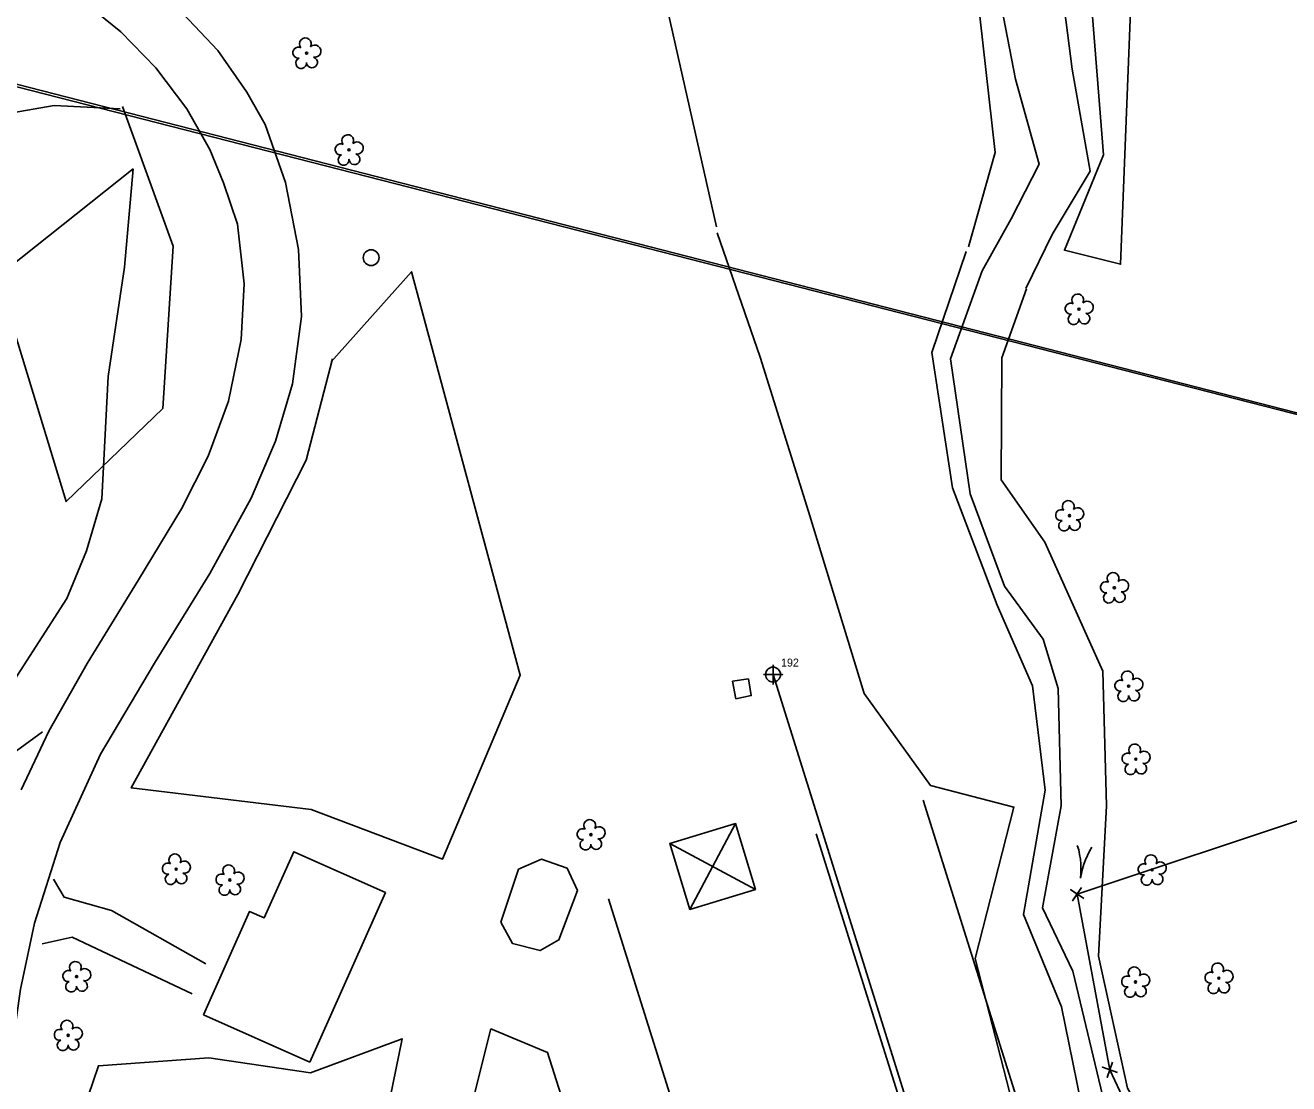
# Model space of a CAD drawing. Extents: x 1380524 to 1382335, y 594765 to 596944.
# Drawn here: x 1381171.1 to 1381565.9, y 595887.1 to 596218 of the extents above; entities that cross this region are included whole.
import ezdxf

# ---------------------------------------------------------------- set-up
doc = ezdxf.new("R2010")
doc.units = 0
for name, color, linetype in [('DTM Contours Major', 7, 'Continuous'), ('DTM Contours Major Text', 7, 'Continuous'), ('DTM Contours Minor Text', 7, 'Continuous'), ('Exist Hydro Jurisdictional Stream or Body of Water', 7, 'Continuous'), ('Exist Roads EOP', 7, 'Continuous'), ('Exist Structure Major Bridge WW', 7, 'Continuous'), ('Exist Utilities Gas UG Line', 7, 'Continuous'), ('Exist Utilities Gas UG Line Cogo Number', 7, 'Continuous'), ('Exist Utilities Gas UG Line Cogo Point CELL', 7, 'Continuous'), ('Exist Utilities Power Tower Text', 7, 'Continuous'), ('Prop Drainage Ditch Base Lines', 7, 'Continuous'), ('Prop Drainage Structure Box Number Symbol CELL', 7, 'Continuous'), ('Prop Drainage Structure Pipe Elbow CELL', 7, 'Continuous'), ('Prop Drainage Structure Plot Symbol 20 Scale CELL', 7, 'Continuous'), ('Prop Earthen Structure Cut Ditch Special Detail Label', 7, 'Continuous'), ('Prop Earthen Structure Ditch Flow Line', 7, 'Continuous'), ('Prop Earthen Structure V Ditch Lateral Detail Label', 7, 'Continuous'), ('Prop Erosion Rip Rap At Embankment Detail CELL', 7, 'Continuous'), ('Prop Plan Preparation Design Box Number Symbol CELL', 7, 'Continuous')]:
    doc.layers.add(name, color=color, linetype=linetype)

# ---------------------------------------------------------------- blocks, each defined once
blk = doc.blocks.new('EXIST VEGETATION TREE')
at = {"layer": 'Prop Erosion Rip Rap At Embankment Detail CELL'}
blk.add_line((0, 0), (0, 0), dxfattribs=at)
blk.add_circle((0, 0), 0.00652, dxfattribs=at)
for centre, radius, start, end in [((-0.0077, 0.0575), 0.0371, 330.16508, 219.71335), ((-0.0521, 0.0031), 0.0345, 62.66361, 279.3457), ((0.051, 0.0118), 0.038, 257.1011, 134.19993), ((-0.0341, -0.0624), 0.0338, 111.56708, 6.23104), ((0.0335, -0.058), 0.034, 181.28216, 74.55999)]:
    blk.add_arc(centre, radius, start, end, dxfattribs=at)
blk = doc.blocks.new('EXIST UTILITIES OTHER POLE')
at = {"layer": 'DTM Contours Major Text'}
blk.add_circle((0, 0), 0.0493, dxfattribs=at)
blk = doc.blocks.new('EXIST HYDRO STREAM FLOW ARROW')
at = {"layer": 'DTM Contours Minor Text'}
blk.add_line((0, 0), (0, 0), dxfattribs=at)
for points in [[(-0.1, 0.04575), (-0.07325, 0.03375), (-0.04475, 0.0245), (-0.0165, 0.01575), (0.01175, 0.0095), (0.041, 0.00475), (0.07075, 0.0015), (0.1, 0)], [(-0.1, -0.04575), (-0.07325, -0.03375), (-0.04475, -0.0245), (-0.0165, -0.01575), (0.01175, -0.0095), (0.041, -0.00475), (0.07075, -0.0015), (0.1, 0)]]:
    blk.add_lwpolyline(points, dxfattribs=at)

msp = doc.modelspace()

# ---------------------------------------------------------------- linework, layer by layer
at = {"layer": 'DTM Contours Major'}
msp.add_lwpolyline([(1381372.49, 595962.18), (1381378.72, 595941.62), (1381399.28, 595947.85), (1381393.05, 595968.41), (1381372.49, 595962.18), (1381399.28, 595947.85), (1381393.05, 595968.41), (1381378.72, 595941.62)], dxfattribs=at)
at = {"layer": 'Exist Hydro Jurisdictional Stream or Body of Water'}
for points in [[(1381483.77, 596135.72), (1381491.96, 596152.52), (1381503.81, 596172.33), (1381498.26, 596204.27), (1381493.33, 596242.46), (1381489.5, 596270.15), (1381491.18, 596292.87), (1381479.48, 596322.14), (1381454.47, 596352.84), (1381438.58, 596366.23), (1381425.98, 596394.97), (1381414.1, 596436.71), (1381399.5, 596471.74), (1381382.49, 596504.52), (1381368.62, 596529.32), (1381356.86, 596549.69), (1381340.72, 596592.72), (1381332.5, 596625.31), (1381329.08, 596649.3), (1381323.28, 596668.67)], [(1381470.05, 596141.17), (1381479.15, 596157.42), (1381487.89, 596174.59), (1381480.55, 596201.17), (1381473.06, 596240.03), (1381476.26, 596270.23), (1381479.45, 596291.3), (1381466.84, 596309.68), (1381447.4, 596346.85), (1381431.33, 596360.89), (1381418.79, 596391.67), (1381403.92, 596432.5), (1381387.45, 596465.68), (1381371.16, 596500.46), (1381359.03, 596523.24), (1381345.11, 596544.14), (1381332.16, 596589.54), (1381322.88, 596621.8), (1381316.31, 596646.98), (1381314.3, 596666.4)], [(1381577.96, 595605.83), (1381583.71, 595643.65), (1381597.79, 595698.93), (1381598.19, 595737), (1381590.93, 595758.1), (1381566.71, 595783.08), (1381549.63, 595827.2), (1381521.68, 595855.93), (1381508.31, 595880.93), (1381498.43, 595922.32), (1381488.98, 595942.12), (1381494.82, 595973.98), (1381493.85, 596010.61), (1381489.16, 596026.09), (1381477.05, 596042.66), (1381466.32, 596071.54), (1381460.24, 596113.74), (1381470.05, 596141.17)], [(1381591.28, 595608.86), (1381593.5, 595640.64), (1381608.3, 595697.05), (1381607.14, 595736.14), (1381600.89, 595770.21), (1381575.06, 595793.44), (1381555.94, 595831.43), (1381528.67, 595862.58), (1381515.5, 595885.72), (1381506.46, 595926.94), (1381508.98, 595973.98), (1381507.81, 596016.05), (1381489.64, 596056.36), (1381476.02, 596075.92), (1381476.25, 596113.98), (1381483.98, 596135.61)]]:
    msp.add_lwpolyline(points, dxfattribs=at)
at = {"layer": 'Exist Roads EOP'}
for points in [[(1381638.84, 595379.18), (1381451.62, 595975.74)], [(1381605.45, 595368.7), (1381418.22, 595965.25)], [(1381540.57, 595348.34), (1381353.34, 595944.89)]]:
    msp.add_lwpolyline(points, dxfattribs=at)
at = {"layer": 'Exist Structure Major Bridge WW'}
for p, q in [((1381499.76, 595946.4), (1381499.76, 595946.4)), ((1381510.01, 595891.46), (1381510.01, 595891.46))]:
    msp.add_line(p, q, dxfattribs=at)
for points in [[(1381501.82, 595944.98), (1381497.7, 595947.81), (1381499.76, 595946.4), (1381498.35, 595944.33), (1381501.17, 595948.46)], [(1381512.36, 595890.61), (1381507.66, 595892.3), (1381510.01, 595891.46), (1381509.16, 595889.11), (1381510.86, 595893.81)]]:
    msp.add_lwpolyline(points, dxfattribs=at)
at = {"layer": 'Exist Utilities Gas UG Line'}
msp.add_lwpolyline([(1381540.8, 595580.17), (1381404.76, 596015.01)], dxfattribs=at)
at = {"layer": 'Exist Utilities Gas UG Line Cogo Point CELL'}
msp.add_lwpolyline([(1381404.76, 596018.01), (1381404.76, 596012.01), (1381404.76, 596015.01), (1381407.76, 596015.01), (1381401.76, 596015.01)], dxfattribs=at)
msp.add_circle((1381404.76, 596015.01), 2.34, dxfattribs=at)
at = {"layer": 'Exist Utilities Power Tower Text'}
for p, q in [((1381499.76, 595946.4), (1381765.24, 596034.56)), ((1381510.01, 595891.46), (1381499.76, 595946.4)), ((1381510.01, 595891.46), (1381524.86, 595859.94))]:
    msp.add_line(p, q, dxfattribs=at)
at = {"layer": 'Prop Drainage Ditch Base Lines'}
for points in [[(1381392.08, 596012.95), (1381397.05, 596013.66), (1381397.93, 596008.46), (1381393.19, 596007.46)], [(1381226.8, 595908.69), (1381260.02, 595893.86), (1381283.67, 595946.84), (1381255, 595959.63), (1381245.77, 595938.95), (1381241.21, 595940.98)]]:
    msp.add_lwpolyline(points, close=True, dxfattribs=at)
at = {"layer": 'Prop Drainage Structure Box Number Symbol CELL'}
for points in [[(1382083.99, 595964.39), (1380966.64, 596251.47), (1381106.82, 596554.99), (1381897.61, 596920.15), (1382148.43, 596473.2)], [(1382083.62, 595964.41), (1382120.69, 595773.82), (1382095.82, 595646.75), (1382010.85, 595488.75), (1381848.52, 595352.32), (1381617.36, 595239.15), (1381304.92, 595184.07), (1381005.77, 595330.75), (1380937.13, 595525.19), (1380768.47, 595849.39), (1380967, 596250.36)]]:
    msp.add_lwpolyline(points, close=True, dxfattribs=at)
at = {"layer": 'Prop Drainage Structure Pipe Elbow CELL'}
for points in [[(1381176.56, 595997.12), (1381157.42, 595983.25), (1381134.69, 595976.29), (1381047.68, 595944), (1381049.6, 595965.94), (1381061.84, 595989.43)], [(1381227.59, 595924.61), (1381198.13, 595941.28), (1381183.3, 595945.43), (1381179.94, 595951.11)], [(1381176.45, 595930.81), (1381185.77, 595932.88), (1381223.23, 595915.2)]]:
    msp.add_lwpolyline(points, dxfattribs=at)
at = {"layer": 'Prop Drainage Structure Plot Symbol 20 Scale CELL'}
msp.add_lwpolyline([(1381319.76, 595937.64), (1381325.24, 595954.14), (1381332.45, 595957.27), (1381340.42, 595954.51), (1381343.66, 595947.51), (1381337.85, 595932.05), (1381331.97, 595928.71), (1381323.33, 595930.98)], close=True, dxfattribs=at)
at = {"layer": 'Prop Earthen Structure Cut Ditch Special Detail Label'}
for points in [[(1381350.25, 596599.71), (1381392.08, 596589.01), (1381455.55, 596462.39), (1381491.49, 596369.91), (1381518.9, 596285.84), (1381513.37, 596143.29), (1381495.81, 596147.64), (1381508.01, 596177.5), (1381501.15, 596264.04), (1381493.24, 596309.84), (1381476.75, 596333.82), (1381457.25, 596364.74), (1381434.82, 596397.71), (1381413.54, 596466.18), (1381382.47, 596526.06), (1381349.37, 596598.57)], [(1381263.88, 596550.5), (1381322.53, 596582.96), (1381347.53, 596524.27), (1381366.83, 596479.87), (1381399.39, 596411.16), (1381434.84, 596339.9), (1381473.87, 596287.88), (1381467.51, 596237.62), (1381474.2, 596178.18), (1381465.81, 596148.7)], [(1381387.07, 596155), (1381371.17, 596225.61), (1381376.7, 596267.4), (1381358.82, 596359.09), (1381310.74, 596446.26), (1381263.45, 596550.77)], [(1381201.51, 596192.62), (1381217.34, 596148.97), (1381214.15, 596098.22), (1381183.9, 596069.06), (1381164.78, 596132.02), (1381109.45, 596101.12), (1381092.76, 596129.65), (1381089.41, 596177.09), (1381180.14, 596192.86), (1381200.77, 596191.89)], [(1381632.41, 595523.63), (1381594.41, 595508.73), (1381570.64, 595578.64), (1381559.09, 595617.64), (1381565.11, 595641.47), (1381533.98, 595685.28), (1381511.68, 595722.95), (1381489.27, 595770.29), (1381496.67, 595816.92), (1381485.72, 595857.08), (1381467.95, 595926.31), (1381480.04, 595973.59), (1381453.92, 595980.31), (1381433.25, 596009.07), (1381415.87, 596065.96), (1381400.69, 596114.25), (1381387.34, 596153.1)], [(1381465.14, 596147.24), (1381454.4, 596115.71), (1381460.79, 596073.39), (1381474.76, 596036.69), (1381485.85, 596011.46), (1381489.74, 595978.87), (1381483.02, 595940.04), (1381494.86, 595911.17), (1381503.32, 595869.73), (1381526.27, 595838.58), (1381548.46, 595817.76), (1381559.9, 595781.05), (1381585.35, 595751.36), (1381590.99, 595713.84), (1381582.97, 595667.85), (1381576.78, 595627.99), (1381575.28, 595604.8), (1381583.28, 595579.61), (1381595.01, 595565.4), (1381637.18, 595526.27), (1381634, 595523.66)], [(1381266.6, 596112.68), (1381291.82, 596140.91), (1381325.76, 596014.83), (1381301.48, 595957.26), (1381260.51, 595972.88), (1381204.23, 595979.6), (1381237.52, 596039.99), (1381258.87, 596082), (1381267.1, 596113.68)], [(1381365.22, 595798.28), (1381326.61, 595780.2), (1381306.84, 595815.2), (1381247.89, 595804.83), (1381210.47, 595847.41), (1381176.29, 595840.7), (1381193.99, 595892.72), (1381228.48, 595895.26), (1381260.25, 595890.55), (1381288.84, 595901.2), (1381279.35, 595854.23), (1381302.68, 595848.54), (1381316.62, 595904.23), (1381334.31, 595896.83), (1381364.84, 595800.74)]]:
    msp.add_lwpolyline(points, dxfattribs=at)
at = {"layer": 'Prop Earthen Structure Ditch Flow Line'}
for points in [[(1380981.36, 596295.45), (1381004.67, 596292.69), (1381047.81, 596288.08), (1381074, 596285.4), (1381107.37, 596279.68), (1381127.78, 596274.86), (1381151.56, 596266.92), (1381170.38, 596258.53), (1381190.52, 596247.28), (1381207.69, 596235.17), (1381231.31, 596210.09), (1381240.31, 596197.1), (1381246.12, 596186.92)], [(1381221.65, 596191.89), (1381211.91, 596204.63), (1381200.96, 596215.94), (1381185.79, 596228.36), (1381172.19, 596237.19), (1381155.12, 596246.05), (1381138.89, 596252.74), (1381122.76, 596257.84), (1381106.86, 596261.65), (1381088.06, 596265.04), (1381068.1, 596268.1), (1381036.65, 596271.91), (1381005.93, 596274.84), (1380977.07, 596278.02)], [(1381169.87, 595978.99), (1381178.46, 595997.27), (1381190.52, 596018.52), (1381206.56, 596044.6), (1381219.93, 596066.83), (1381228.31, 596083.28), (1381234.65, 596100.51), (1381238.64, 596119.77), (1381239.56, 596137.16), (1381237.45, 596155.75), (1381233.1, 596168.76), (1381228.75, 596179.15), (1381221.65, 596191.89)], [(1381246.12, 596186.92), (1381252.41, 596168.85), (1381256.49, 596147.87), (1381257.46, 596126.94), (1381254.67, 596105.85), (1381249.36, 596087.97), (1381241.72, 596070.15), (1381228.75, 596046.59), (1381211.47, 596018.6), (1381194.69, 595990.16), (1381182.03, 595962.49), (1381174.06, 595937.34), (1381169.64, 595916.69), (1381167.03, 595898.25), (1381165.59, 595870.2), (1381166.09, 595853.66), (1381169.08, 595819.04), (1381175.35, 595780.97), (1381183.42, 595743.09), (1381187.72, 595727.78)]]:
    msp.add_lwpolyline(points, dxfattribs=at)
at = {"layer": 'Prop Earthen Structure V Ditch Lateral Detail Label'}
for points in [[(1381204.84, 596173.1), (1381121.29, 596106.69), (1381063.64, 596063.01), (1381003.83, 596016.76), (1380944.89, 595972.93), (1380887.72, 595928.05), (1380858.51, 595907.23)], [(1381124.76, 595976.32), (1381134.27, 595979.78), (1381154.09, 595992.3), (1381184.09, 596038.74), (1381190.32, 596053.74), (1381195.02, 596069.99), (1381197.09, 596108.17), (1381202.1, 596142.4), (1381204.84, 596173.1)]]:
    msp.add_lwpolyline(points, dxfattribs=at)

# ---------------------------------------------------------------- block references
at = {"layer": 'DTM Contours Major Text', "xscale": 50, "yscale": 50}
msp.add_blockref('EXIST UTILITIES OTHER POLE', (1381279.19, 596145.33), dxfattribs=at)
at = {"layer": 'Prop Erosion Rip Rap At Embankment Detail CELL', "xscale": 50, "yscale": 50}
for p in [(1381259.05, 596209.27), (1381272.28, 596179.01), (1381500.35, 596129.22), (1381497.39, 596064.68), (1381511.4, 596042.16), (1381515.87, 596011.37), (1381518.13, 595988.56), (1381347.87, 595964.97), (1381218.28, 595954.21), (1381523.19, 595953.95), (1381235.06, 595950.8), (1381187.18, 595920.6), (1381544.05, 595920.1), (1381518, 595918.91), (1381184.53, 595902.25)]:
    msp.add_blockref('EXIST VEGETATION TREE', p, dxfattribs=at)
at = {"layer": 'Prop Plan Preparation Design Box Number Symbol CELL', "xscale": 49.99999999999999, "yscale": 50.00000000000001, "rotation": -97.23264166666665}
msp.add_blockref('EXIST HYDRO STREAM FLOW ARROW', (1381501.47, 595956.38), dxfattribs=at)

# ---------------------------------------------------------------- texts
at = {"layer": 'Exist Utilities Gas UG Line Cogo Number'}
msp.add_text('192', height=2.5, dxfattribs=at).set_placement((1381407.26, 596017.51))

doc.saveas('drawing.dxf')
